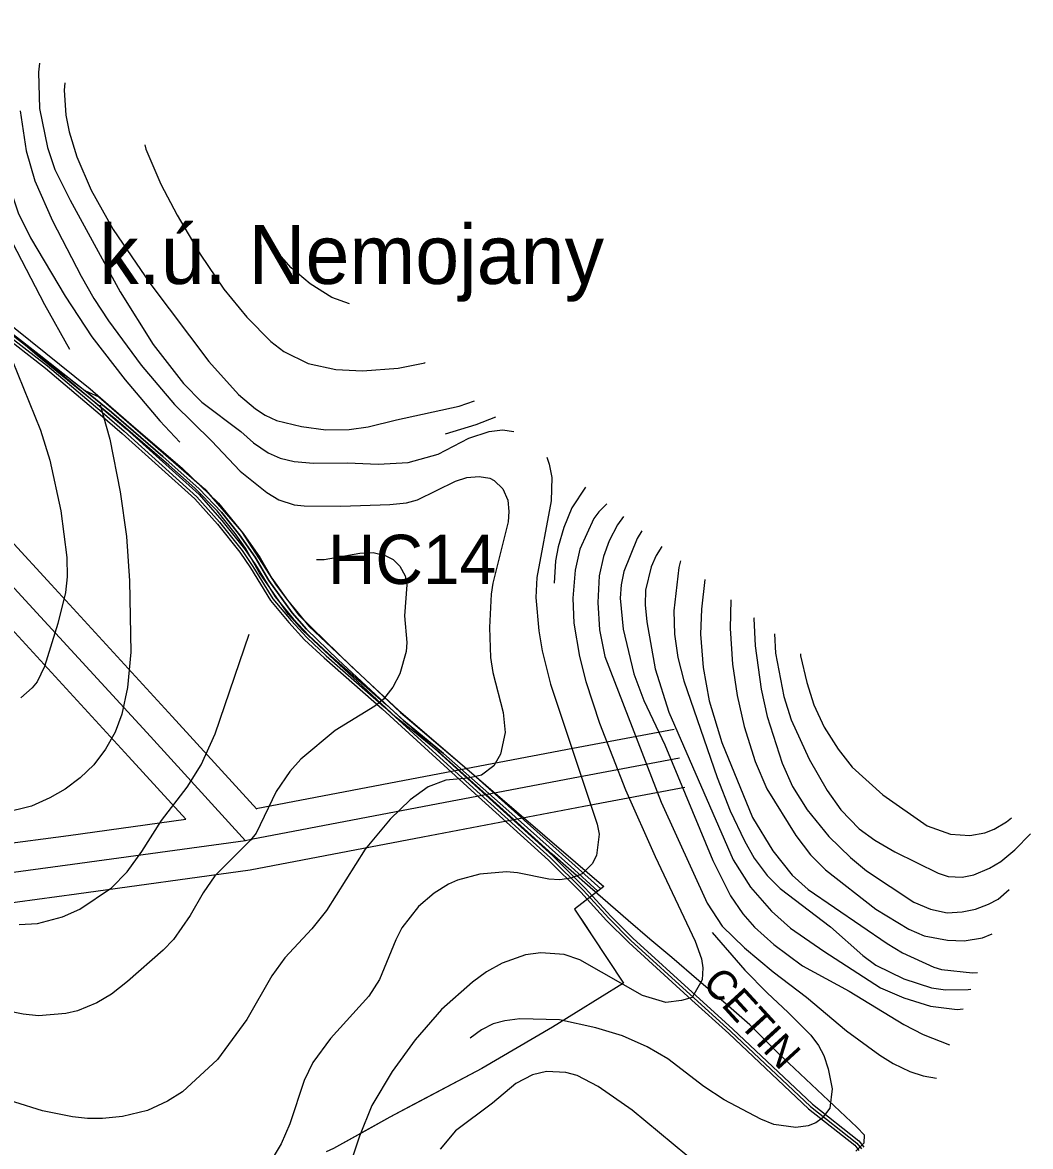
# Model space of a CAD drawing. Extents: x -1900516 to -575031, y -3809306 to -1157387.
# Drawn here: x -576727 to -576215, y -1158034 to -1157464 of the extents above; entities that cross this region are included whole.
import ezdxf

# ---------------------------------------------------------------- set-up
doc = ezdxf.new("R2010")
doc.units = 0
for name, color, linetype in [('01_OBVOD PÚ', 7, 'Continuous'), ('01_SPRÁV_HRANICE', 7, 'Continuous'), ('01_VRSTEVNICE', 7, 'Continuous'), ('02_KULTURY STAV', 7, 'Continuous'), ('03_PC_POPIS_STAV', 7, 'Continuous'), ('03_PC_STAV', 7, 'Continuous'), ('04_ZPF_OP_ORGAN', 7, 'Continuous'), ('07_ELEKTRO', 7, 'Continuous'), ('07_OCH_P A POPISY TI', 7, 'Continuous'), ('07_SDĚLOVACÍ', 7, 'Continuous')]:
    doc.layers.add(name, color=color, linetype=linetype)

msp = doc.modelspace()

# ---------------------------------------------------------------- linework, layer by layer
at = {"layer": '01_OBVOD PÚ'}
msp.add_lwpolyline([(-576728.04, -1157624.7), (-576725.06, -1157627.04), (-576722.43, -1157629.11), (-576718.49, -1157632.21), (-576717.18, -1157633.23), (-576711.95, -1157637.34), (-576706.32, -1157641.76), (-576704.25, -1157643.39), (-576701.08, -1157645.87), (-576695.26, -1157650.44), (-576688.08, -1157653.73), (-576634.44, -1157700.33), (-576615.59, -1157721.97), (-576598.08, -1157749.21), (-576586.54, -1157764.45), (-576559.98, -1157790.42), (-576535.99, -1157812.74), (-576431.68, -1157902.32), (-576433.12, -1157903.44), (-576446.46, -1157913.81), (-576440.6, -1157922.65), (-576437.53, -1157927.29), (-576429.6, -1157939.25), (-576421.57, -1157951.36), (-576457.68, -1157973.76), (-576493.58, -1157994.61), (-576530.49, -1158014.16), (-576540.36, -1158019.43), (-576550.05, -1158024.84), (-576568.92, -1158035.36)], dxfattribs=at)
at = {"layer": '01_SPRÁV_HRANICE'}
for p, q in [((-576731.39, -1157622.07), (-576718.49, -1157632.21)), ((-576718.49, -1157632.21), (-576695.26, -1157650.44)), ((-576695.26, -1157650.44), (-576688.08, -1157653.73)), ((-576633.78, -1157701.05), (-576615.59, -1157721.97)), ((-576615.59, -1157721.97), (-576598.08, -1157749.21)), ((-576598.08, -1157749.21), (-576586.54, -1157764.45)), ((-576586.54, -1157764.45), (-576559.98, -1157790.42)), ((-576559.98, -1157790.42), (-576535.99, -1157812.74)), ((-576535.99, -1157812.74), (-576431.68, -1157902.32)), ((-576433.12, -1157903.44), (-576446.46, -1157913.81)), ((-576431.68, -1157902.32), (-576433.12, -1157903.44)), ((-576446.46, -1157913.81), (-576421.57, -1157951.36))]:
    msp.add_line(p, q, dxfattribs=at)
for points in [[(-576688.08, -1157653.73), (-576661.26, -1157677.03), (-576634.44, -1157700.33), (-576633.78, -1157701.05)], [(-576421.57, -1157951.36), (-576457.68, -1157973.76), (-576493.58, -1157994.61)], [(-576493.58, -1157994.61), (-576540.36, -1158019.43), (-576568.92, -1158035.36), (-576572.73, -1158036.92)]]:
    msp.add_lwpolyline(points, dxfattribs=at)
at = {"layer": '01_VRSTEVNICE'}
for points in [[(-576744.91, -1157463.58), (-576748.9, -1157474.22), (-576751.01, -1157491.15), (-576750.02, -1157513.73), (-576747.62, -1157533.48), (-576744.94, -1157546.18), (-576739.16, -1157561.7), (-576715.74, -1157606.85), (-576703.04, -1157629.42)], [(-576738.47, -1157468.58), (-576739.02, -1157469.99), (-576740.85, -1157478.45), (-576741.84, -1157486.92), (-576741.84, -1157501.03), (-576740.01, -1157519.37), (-576735.77, -1157540.53), (-576729.14, -1157560.28), (-576722.79, -1157572.98), (-576705.16, -1157602.61), (-576691.75, -1157623.21), (-576674.82, -1157644.94), (-576657.18, -1157665.82), (-576647.03, -1157676.69)], [(-576718.26, -1157484.26), (-576718.84, -1157488.89), (-576718.28, -1157507.24), (-576714.19, -1157526.99), (-576710.38, -1157538.28), (-576702.62, -1157553.79), (-576677.36, -1157600.36), (-576660.57, -1157627.16), (-576645.19, -1157646.92), (-576635.74, -1157656.37), (-576615.99, -1157671.32), (-576609.49, -1157676.97), (-576602.16, -1157682.05), (-576595.95, -1157684.73), (-576588.9, -1157686.42), (-576579.02, -1157687.41), (-576561.81, -1157687.13), (-576546.29, -1157687.83), (-576531.05, -1157686.99), (-576515.81, -1157682.75), (-576500.15, -1157674.57), (-576489.85, -1157671.32), (-576483.08, -1157670.48), (-576477.35, -1157671.22)], [(-576705.41, -1157494.23), (-576705.72, -1157497.92), (-576704.87, -1157510.62), (-576703.18, -1157519.09), (-576699.37, -1157531.78), (-576692.04, -1157548.72), (-576680.89, -1157568.61), (-576662.26, -1157595.98), (-576632.21, -1157635.77), (-576617.11, -1157652.42), (-576608.51, -1157659.76), (-576603.57, -1157663), (-576597.93, -1157665.68), (-576585.23, -1157668.79), (-576572.81, -1157670.34), (-576560.96, -1157670.2), (-576551.36, -1157668.93), (-576536.97, -1157665.26), (-576505.09, -1157658.34), (-576497.29, -1157655.75)], [(-576728.15, -1157508.36), (-576725.05, -1157528.68), (-576720.54, -1157543.92), (-576711.65, -1157564.24), (-576697.11, -1157592.46), (-576690.62, -1157603.74), (-576683.15, -1157615.03), (-576666.64, -1157637.6), (-576649.71, -1157657.5), (-576630.94, -1157675.98), (-576616.41, -1157691.36), (-576602.86, -1157702.22), (-576596.66, -1157706.03), (-576588.9, -1157708.43), (-576583.82, -1157709), (-576565.19, -1157709.14), (-576540.36, -1157708.29), (-576531.89, -1157707.45), (-576526.25, -1157705.89), (-576507.06, -1157696.44), (-576501.14, -1157694.6), (-576494.93, -1157694.04), (-576489.57, -1157694.89), (-576487.31, -1157696.16), (-576482.94, -1157700.39), (-576480.4, -1157706.18), (-576479.83, -1157711.82), (-576480.25, -1157717.18), (-576488.01, -1157748.22), (-576488.86, -1157753.86), (-576489.71, -1157770.8), (-576489.14, -1157786.03), (-576488.01, -1157793.65), (-576482.79, -1157813.97), (-576481.67, -1157824.13), (-576484.06, -1157835.13), (-576487.59, -1157840.92), (-576493.8, -1157845.72), (-576500.57, -1157847.27), (-576511.86, -1157848.26), (-576520.89, -1157851.64), (-576529.92, -1157858.27), (-576540.22, -1157868.15), (-576552.92, -1157883.25), (-576572.53, -1157914.43), (-576579.87, -1157923.74), (-576593.69, -1157938.41), (-576600.18, -1157947.58), (-576612.88, -1157969.74), (-576627.84, -1157990.05), (-576645.61, -1158006.56), (-576653.23, -1158011.22), (-576663.39, -1158016.01), (-576676.09, -1158018.98), (-576686.25, -1158020.11), (-576693.87, -1158020.11), (-576701.49, -1158019.26), (-576716.73, -1158016.16), (-576744.94, -1158007.41)], [(-576664.84, -1157525.71), (-576664.24, -1157527.83), (-576656.62, -1157545.61), (-576648.3, -1157561.41), (-576636.58, -1157581.17), (-576624.59, -1157598.95), (-576612.88, -1157613.2), (-576600.75, -1157625.61), (-576594.12, -1157630.69), (-576581.84, -1157636.76), (-576567.73, -1157639.72), (-576554.19, -1157640.43), (-576536.13, -1157639.02), (-576522.58, -1157636.33), (-576522.38, -1157636.27)], [(-576560.84, -1157606.43), (-576569.71, -1157603.18), (-576580.85, -1157596.26), (-576590.45, -1157588.22), (-576599.05, -1157578.34), (-576601.3, -1157575.03)], [(-576732.1, -1157635.06), (-576717.71, -1157670.62), (-576713.06, -1157685.86), (-576707.41, -1157711.54), (-576704.31, -1157735.24), (-576704.17, -1157745.12), (-576705.02, -1157753.02), (-576708.96, -1157768.82), (-576715.74, -1157790.55), (-576719.41, -1157798.31), (-576721.95, -1157801.41), (-576727.73, -1157806.49)], [(-576687.38, -1157657.78), (-576682.58, -1157675.14), (-576677.22, -1157701.94), (-576674.12, -1157724.52), (-576672.56, -1157747.09), (-576671.86, -1157783.21), (-576673.55, -1157801.27), (-576676.51, -1157814.82), (-576679.9, -1157823.85), (-576684.7, -1157832.59), (-576690.62, -1157840.5), (-576697.54, -1157847.13), (-576705.16, -1157852.77), (-576713.06, -1157857.28), (-576722.37, -1157861.52), (-576736.76, -1157865.04)], [(-576486.68, -1157663.98), (-576496.62, -1157667.94), (-576512.28, -1157672.59)], [(-576460.57, -1157684.25), (-576459.37, -1157687.83), (-576458.1, -1157694.61), (-576458.39, -1157706.46), (-576465.72, -1157745.4), (-576466.15, -1157755.56), (-576464.59, -1157772.49), (-576462.9, -1157782.65), (-576458.81, -1157799.58), (-576434.96, -1157870.69), (-576433.98, -1157875.77), (-576435.39, -1157886.49), (-576437.5, -1157890.72), (-576442.72, -1157895.8), (-576448.37, -1157898.06), (-576454.01, -1157898.91), (-576459.66, -1157898.62), (-576475.46, -1157895.38), (-576481.1, -1157894.82), (-576494.65, -1157895.94), (-576505.93, -1157899.05), (-576510.45, -1157901.02), (-576517.79, -1157905.68), (-576525.69, -1157912.45), (-576534.15, -1157923.32), (-576537.26, -1157929.38), (-576545.58, -1157949.42), (-576550.94, -1157958.03), (-576570.41, -1157979.47), (-576579.44, -1157991.6), (-576583.82, -1158000.78), (-576591.15, -1158022.79), (-576595.53, -1158032.95), (-576602.58, -1158044.8)], [(-576440.88, -1157699.53), (-576447.89, -1157710.02), (-576451.89, -1157720), (-576454.86, -1157729.88), (-576456.13, -1157736.93), (-576456.83, -1157748.22)], [(-576440.88, -1157699.53), (-576447.89, -1157710.02), (-576451.89, -1157720), (-576454.86, -1157729.88), (-576456.13, -1157736.93), (-576456.83, -1157748.22)], [(-576430.05, -1157707.93), (-576434.12, -1157711.96), (-576436.66, -1157715.35), (-576443.85, -1157731.01), (-576446.25, -1157741.73), (-576447.38, -1157755.84), (-576446.82, -1157768.54), (-576443.99, -1157785.47), (-576440.75, -1157798.17), (-576433.83, -1157819.33), (-576420.71, -1157853.19), (-576405.62, -1157887.06), (-576385.3, -1157929.95), (-576382.05, -1157938.98), (-576381.35, -1157943.49), (-576381.63, -1157949.7), (-576386.85, -1157958.59), (-576392.21, -1157960.14), (-576400.11, -1157961.13), (-576411.97, -1157957.6), (-576443.85, -1157939.54), (-576451.75, -1157936.86), (-576463.61, -1157935.87), (-576471.51, -1157937), (-576483.36, -1157941.24), (-576491.26, -1157945.61), (-576498.31, -1157950.83), (-576514.12, -1157964.66), (-576527.38, -1157980.18), (-576539.09, -1157996.26), (-576549.39, -1158013.48), (-576555.74, -1158029), (-576561.52, -1158046.35)], [(-576421.69, -1157714.42), (-576424.66, -1157718.59), (-576428.9, -1157726.78), (-576431.86, -1157734.68), (-576433.98, -1157744.55), (-576434.68, -1157758.1), (-576433.83, -1157771.92), (-576431.15, -1157785.47), (-576402.51, -1157859.4), (-576379.09, -1157910.76), (-576371.47, -1157922.47), (-576360.18, -1157933.48), (-576345.65, -1157945.61), (-576328.72, -1157958.45), (-576308.4, -1157975.52), (-576291.47, -1157987.94), (-576284.7, -1157992.17), (-576276.23, -1157996.12), (-576269.46, -1157998.38), (-576262.63, -1157999.63)], [(-576412.33, -1157721.68), (-576414.79, -1157725.51), (-576421.42, -1157742.29), (-576422.83, -1157749.07), (-576423.39, -1157755.84), (-576421.84, -1157771.64), (-576416.34, -1157794.22), (-576411.4, -1157807.76), (-576400.68, -1157830.34), (-576376.27, -1157889.03), (-576367.24, -1157907.09), (-576361.03, -1157916.12), (-576355.1, -1157922.89), (-576345.23, -1157931.64), (-576330.7, -1157942.51), (-576306.99, -1157955.49), (-576279.34, -1157972.42), (-576269.46, -1157977.35), (-576256.11, -1157982.67)], [(-576402.17, -1157729.57), (-576405.05, -1157734.25), (-576407.59, -1157740.04), (-576410.41, -1157751.89), (-576410.7, -1157759.23), (-576409.85, -1157767.97), (-576405.62, -1157791.68), (-576398.56, -1157813.69), (-576365.97, -1157888.75), (-576357.08, -1157902.58), (-576346.5, -1157914.85), (-576336.9, -1157923.46), (-576319.97, -1157935.17), (-576291.19, -1157953.65), (-576279.34, -1157958.87), (-576265.79, -1157963.1), (-576252.25, -1157964.8), (-576249.1, -1157964.44)], [(-576577.56, -1157736.23), (-576573.66, -1157736.23), (-576555.6, -1157732.98), (-576548.83, -1157732.7), (-576542.62, -1157734.25), (-576538.67, -1157736.23), (-576535.28, -1157739.61), (-576532.46, -1157744.55), (-576531.61, -1157749.07), (-576532.88, -1157764.87), (-576531.75, -1157778.42), (-576532.04, -1157782.93), (-576535.28, -1157794.22), (-576538.81, -1157800.99), (-576543.46, -1157807.2), (-576547.98, -1157810.72), (-576568.01, -1157823), (-576585.51, -1157837.67), (-576591.15, -1157843.88), (-576598.07, -1157854.04), (-576608.22, -1157875.2), (-576611.05, -1157878.73), (-576629.25, -1157896.79), (-576635.17, -1157905.54), (-576641.66, -1157916.97), (-576650.27, -1157929.1), (-576655.49, -1157934.6), (-576673.55, -1157950.55), (-576681.73, -1157956.9), (-576689.07, -1157961.27), (-576698.95, -1157965.36), (-576704.87, -1157966.77), (-576718.7, -1157967.9), (-576726.6, -1157967.05), (-576736.48, -1157965.08)], [(-576392.64, -1157736.97), (-576393.62, -1157740.32), (-576396.16, -1157762.33), (-576395.74, -1157774.18), (-576394.05, -1157786.03), (-576390.94, -1157797.89), (-576374.15, -1157846.99), (-576367.52, -1157863.92), (-576360.18, -1157879.16), (-576355.25, -1157887.9), (-576348.76, -1157896.65), (-576342.12, -1157903.28), (-576316.59, -1157922.75), (-576300.08, -1157937.28), (-576293.45, -1157942.22), (-576279.34, -1157949.14), (-576265.23, -1157953.65), (-576258.18, -1157954.78), (-576246.6, -1157954.64), (-576245.24, -1157954.39)], [(-576380.42, -1157746.44), (-576382.05, -1157761.48), (-576382.48, -1157774.18), (-576381.21, -1157791.11), (-576378.1, -1157808.04), (-576371.75, -1157829.21), (-576356.09, -1157867.3), (-576345.79, -1157884.23), (-576336.06, -1157896.51), (-576327.87, -1157903.71), (-576287.8, -1157931.22), (-576279.9, -1157936.02), (-576264.1, -1157943.21), (-576260.15, -1157944.34), (-576244.35, -1157946.03), (-576241.95, -1157945.86)], [(-576367.12, -1157756.77), (-576367.52, -1157771.36), (-576366.25, -1157789.42), (-576363.85, -1157805.22), (-576360.33, -1157821.03), (-576354.82, -1157838.8), (-576348.9, -1157852.63), (-576334.08, -1157876.33), (-576326.74, -1157886.21), (-576319.13, -1157893.83), (-576293.45, -1157913.72), (-576276.8, -1157923.88), (-576268.9, -1157927.27), (-576257.05, -1157929.53), (-576248.58, -1157929.81), (-576239.27, -1157928.26), (-576234.4, -1157926.23)], [(-576355.37, -1157765.88), (-576355.39, -1157766.28), (-576354.82, -1157780.11), (-576351.72, -1157802.12), (-576348.61, -1157815.95), (-576341.14, -1157839.65), (-576335.78, -1157851.5), (-576328.44, -1157863.35), (-576317.43, -1157876.9), (-576306.43, -1157887.62), (-576298.24, -1157894.39), (-576274.26, -1157910.2), (-576265.79, -1157913.86), (-576257.33, -1157915.56), (-576249.71, -1157915.13), (-576242.94, -1157913.86), (-576236.31, -1157911.32), (-576231.37, -1157908.64), (-576225.79, -1157903.84)], [(-576728.58, -1157921.62), (-576719.27, -1157921.06), (-576706.57, -1157917.67), (-576697.82, -1157913.72), (-576681.73, -1157903), (-576673.69, -1157894.82), (-576666.35, -1157884.52), (-576656.34, -1157868.71), (-576643.22, -1157851.78), (-576636.16, -1157840.5), (-576629.11, -1157824.69), (-576611.77, -1157774.08)], [(-576345.01, -1157773.93), (-576344.38, -1157783.78), (-576340.29, -1157805.79), (-576336.48, -1157817.64), (-576327.31, -1157837.67), (-576318.28, -1157853.48), (-576311.22, -1157863.35), (-576302.05, -1157872.95), (-576294.01, -1157878.73), (-576283.85, -1157884.66), (-576261.84, -1157895.52), (-576256.76, -1157897.21), (-576249.71, -1157897.5), (-576243.78, -1157896.37), (-576235.74, -1157892.98), (-576229.96, -1157889.59), (-576222.9, -1157883.67), (-576214.94, -1157875.61)], [(-576331.78, -1157784.19), (-576331.68, -1157785.19), (-576328.58, -1157798.73), (-576325.05, -1157810.02), (-576319.69, -1157821.31), (-576312.64, -1157832.59), (-576305.44, -1157841.62), (-576289.92, -1157855.73), (-576267.49, -1157871.53), (-576255.64, -1157875.77), (-576245.76, -1157876.33), (-576238.14, -1157875.06), (-576233.34, -1157873.09), (-576227.13, -1157869.42), (-576224.57, -1157867.4)], [(-576376.55, -1157925.57), (-576360.04, -1157944.76), (-576348.76, -1157956.33), (-576338.03, -1157966.21), (-576326.46, -1157977.78), (-576322.65, -1157983), (-576319.97, -1157988.08), (-576317.71, -1157994.85), (-576315.74, -1158005.01), (-576316.87, -1158014.74), (-576320.68, -1158019.97), (-576323.92, -1158022.22), (-576327.88, -1158023.77), (-576334.08, -1158024.6), (-576345.23, -1158023.07), (-576351.86, -1158020.39), (-576370.48, -1158010.51), (-576380.78, -1158003.74), (-576399.13, -1157989.77), (-576409.71, -1157983.7), (-576422.12, -1157978.06), (-576435.67, -1157974.11), (-576454.15, -1157970.02), (-576474.33, -1157969.45), (-576481.95, -1157970.44), (-576487.87, -1157971.99), (-576493.8, -1157974.96), (-576499.58, -1157979.33)], [(-576382.62, -1158044.66), (-576417.33, -1158015.87), (-576434.54, -1158003.88), (-576445.26, -1157998.24), (-576450.91, -1157996.68), (-576460.78, -1157996.26), (-576467.84, -1157997.81), (-576476.3, -1158002.33), (-576488.16, -1158012.21), (-576506.92, -1158026.31), (-576514.82, -1158035.63)]]:
    msp.add_lwpolyline(points, dxfattribs=at)
at = {"layer": '02_KULTURY STAV'}
msp.add_lwpolyline([(-576728.04, -1157624.7), (-576725.06, -1157627.04), (-576722.43, -1157629.11), (-576718.49, -1157632.21), (-576717.18, -1157633.23), (-576711.95, -1157637.34), (-576706.32, -1157641.76), (-576704.25, -1157643.39), (-576701.08, -1157645.87), (-576695.28, -1157650.41), (-576695.21, -1157650.47), (-576681.63, -1157661.5), (-576655.57, -1157684), (-576637.15, -1157700.31), (-576625.84, -1157712.17), (-576616.74, -1157723.66), (-576608.74, -1157735.11), (-576601.7, -1157746.91), (-576589.96, -1157763.27), (-576582.6, -1157771.64), (-576566.5, -1157787.11), (-576533.42, -1157818.03), (-576513.15, -1157834.81), (-576481.45, -1157862.74), (-576448.48, -1157892.13), (-576434.68, -1157904.65), (-576446.46, -1157913.81), (-576440.6, -1157922.65), (-576437.53, -1157927.29), (-576429.6, -1157939.25), (-576421.57, -1157951.36), (-576457.68, -1157973.76), (-576493.58, -1157994.61), (-576530.49, -1158014.16), (-576540.36, -1158019.43), (-576550.05, -1158024.84), (-576568.92, -1158035.36)], dxfattribs=at)
msp.add_lwpolyline([(-576695.21, -1157650.47), (-576688.08, -1157653.73), (-576634.44, -1157700.33), (-576615.59, -1157721.97), (-576598.08, -1157749.21), (-576586.54, -1157764.45), (-576559.98, -1157790.42), (-576535.99, -1157812.74), (-576431.68, -1157902.32), (-576433.12, -1157903.44), (-576434.68, -1157904.65), (-576448.48, -1157892.13), (-576481.45, -1157862.74), (-576513.15, -1157834.81), (-576533.42, -1157818.03), (-576566.5, -1157787.11), (-576582.6, -1157771.64), (-576589.96, -1157763.27), (-576601.7, -1157746.91), (-576608.74, -1157735.11), (-576616.74, -1157723.66), (-576625.84, -1157712.17), (-576637.15, -1157700.31), (-576655.57, -1157684), (-576681.63, -1157661.5)], close=True, dxfattribs=at)
at = {"layer": '03_PC_STAV'}
msp.add_lwpolyline([(-576782.18, -1157576.41), (-576761.16, -1157594.51), (-576692.46, -1157649.63), (-576670.36, -1157668.91), (-576645.86, -1157689.9), (-576627.28, -1157707.7), (-576614.87, -1157722.99), (-576606.14, -1157735.47), (-576600.23, -1157745.64), (-576592.31, -1157756.83), (-576581.51, -1157770.07), (-576552.51, -1157797.3), (-576534.96, -1157813.88), (-576501.47, -1157842.44), (-576433.12, -1157903.44)], dxfattribs=at)
at = {"layer": '04_ZPF_OP_ORGAN'}
for points in [[(-576303.7, -1158036.7), (-576299.5, -1158032.5), (-576299.2, -1158028.5), (-576303.1, -1158024.5), (-576323.25, -1158005.55), (-576343.4, -1157986.6), (-576357.5, -1157972.5), (-576369.7, -1157961.9), (-576383.4, -1157950.1), (-576397.1, -1157938.3), (-576408.2, -1157928.95), (-576419.3, -1157919.6), (-576438.6, -1157902.75), (-576457.9, -1157885.9), (-576486.35, -1157860.2), (-576514.8, -1157834.5), (-576526, -1157825.4), (-576537.2, -1157816.3), (-576570.9, -1157784.9), (-576584.6, -1157772.1), (-576591.8, -1157764.1), (-576599.2, -1157753.52), (-576606.6, -1157742.94), (-576613.66, -1157730.55), (-576618.8, -1157723), (-576623.45, -1157717.3), (-576628.1, -1157711.6), (-576639.3, -1157700.1), (-576652.6, -1157688.4), (-576666, -1157676.8), (-576679.4, -1157665.2), (-576699.4, -1157648.95), (-576719.4, -1157632.7), (-576726.6, -1157626.5), (-576737.84, -1157617.37)], [(-576570.9, -1157784.9), (-576584.6, -1157772.1), (-576591.8, -1157764.1), (-576599.2, -1157753.52), (-576606.6, -1157742.94), (-576613.66, -1157730.55), (-576618.8, -1157723), (-576623.45, -1157717.3), (-576628.1, -1157711.6), (-576639.3, -1157700.1), (-576652.6, -1157688.4), (-576666, -1157676.8), (-576679.4, -1157665.2), (-576699.4, -1157648.95), (-576719.4, -1157632.7), (-576726.6, -1157626.5), (-576737.84, -1157617.37)], [(-576303.7, -1158036.7), (-576299.5, -1158032.5), (-576299.2, -1158028.5), (-576303.1, -1158024.5), (-576323.25, -1158005.55), (-576343.4, -1157986.6), (-576357.5, -1157972.5), (-576369.7, -1157961.9), (-576383.4, -1157950.1), (-576397.1, -1157938.3), (-576408.2, -1157928.95), (-576419.3, -1157919.6), (-576438.6, -1157902.75), (-576457.9, -1157885.9), (-576486.35, -1157860.2), (-576514.8, -1157834.5), (-576526, -1157825.4), (-576537.2, -1157816.3), (-576570.9, -1157784.9)]]:
    msp.add_lwpolyline(points, dxfattribs=at)
at = {"layer": '07_ELEKTRO'}
for points in [[(-576829.65, -1157643.61), (-576786.08, -1157691.03), (-576723.45, -1157759.12), (-576661.94, -1157826.12), (-576613.64, -1157879.01)], [(-576393.24, -1157837.13), (-576444.58, -1157846.72), (-576526.46, -1157862.4)], [(-576526.46, -1157862.4), (-576610.73, -1157878.46), (-576613.64, -1157879.01)], [(-576613.64, -1157879.01), (-576701.48, -1157891.16), (-576783, -1157902.14), (-576868.21, -1157913.92), (-576958.94, -1157926.41), (-577060.41, -1157940.16), (-577166.82, -1157954.4), (-577258.94, -1157956.97), (-577319.09, -1157965.17), (-577363.1, -1157971.3), (-577443.48, -1157983.02), (-577522.09, -1157993.86), (-577610.84, -1158006.39), (-577703.33, -1158019.18), (-577796.56, -1158031.66)]]:
    msp.add_lwpolyline(points, dxfattribs=at)
at = {"layer": '07_OCH_P A POPISY TI'}
for p, q in [((-576447.37, -1157831.98), (-576395.99, -1157822.38)), ((-576529.27, -1157847.67), (-576447.37, -1157831.98)), ((-576608.21, -1157862.71), (-576529.27, -1157847.67)), ((-576441.79, -1157861.46), (-576390.48, -1157851.87)), ((-576523.64, -1157877.13), (-576441.79, -1157861.46)), ((-576703.51, -1157876.3), (-576643.95, -1157868.06)), ((-576785.03, -1157887.28), (-576703.51, -1157876.3)), ((-576611.21, -1157893.82), (-576523.64, -1157877.13)), ((-576699.45, -1157906.02), (-576611.21, -1157893.82)), ((-576780.97, -1157917), (-576699.45, -1157906.02))]:
    msp.add_line(p, q, dxfattribs=at)
for points in [[(-576737.44, -1157618.14), (-576713.28, -1157636.7), (-576685.53, -1157660.32), (-576674.27, -1157669.93), (-576637.24, -1157703.29), (-576625.62, -1157716.38), (-576614.14, -1157730.75), (-576608.6, -1157738.91), (-576598.57, -1157755.26), (-576589.34, -1157766.3), (-576581.5, -1157774.85), (-576571.63, -1157784), (-576542.24, -1157809.87), (-576495.2, -1157852.75), (-576457.62, -1157886.7), (-576441.09, -1157903.04), (-576428.08, -1157917.39), (-576416.93, -1157928.56), (-576384.85, -1157957.69), (-576366.08, -1157974.76), (-576325.69, -1158012.86), (-576302.1, -1158031.48), (-576299.6, -1158034.63)], [(-576739.28, -1157620.52), (-576715.16, -1157639.04), (-576687.47, -1157662.6), (-576676.25, -1157672.19), (-576639.38, -1157705.41), (-576627.92, -1157718.32), (-576616.56, -1157732.53), (-576611.12, -1157740.53), (-576601.01, -1157757.02), (-576591.6, -1157768.28), (-576583.62, -1157776.97), (-576573.65, -1157786.22), (-576544.24, -1157812.11), (-576497.22, -1157854.97), (-576459.68, -1157888.88), (-576443.25, -1157905.12), (-576430.26, -1157919.45), (-576419.01, -1157930.74), (-576386.87, -1157959.91), (-576368.12, -1157976.96), (-576327.65, -1158015.14), (-576304.24, -1158033.62), (-576302.1, -1158036.31)], [(-576818.6, -1157633.46), (-576775.04, -1157680.88), (-576712.4, -1157748.97), (-576650.88, -1157815.99), (-576607.88, -1157863.07)], [(-576840.69, -1157653.76), (-576797.12, -1157701.18), (-576734.49, -1157769.27), (-576673, -1157836.25), (-576643.95, -1157868.06)]]:
    msp.add_lwpolyline(points, dxfattribs=at)
at = {"layer": '07_SDĚLOVACÍ'}
msp.add_lwpolyline([(-576738.36, -1157619.33), (-576714.22, -1157637.87), (-576686.5, -1157661.46), (-576675.26, -1157671.06), (-576638.31, -1157704.35), (-576626.77, -1157717.35), (-576615.35, -1157731.64), (-576609.86, -1157739.72), (-576599.79, -1157756.14), (-576590.47, -1157767.29), (-576582.56, -1157775.91), (-576572.64, -1157785.11), (-576543.24, -1157810.99), (-576496.21, -1157853.86), (-576458.65, -1157887.79), (-576442.17, -1157904.08), (-576429.17, -1157918.42), (-576417.97, -1157929.65), (-576385.86, -1157958.8), (-576367.1, -1157975.86), (-576326.67, -1158014), (-576303.17, -1158032.55), (-576300.85, -1158035.47)], dxfattribs=at)

# ---------------------------------------------------------------- texts
at = {"layer": '01_SPRÁV_HRANICE'}
msp.add_text('k.ú. Nemojany', height=30, dxfattribs=at).set_placement((-576687.93, -1157596.34))
at = {"layer": '03_PC_POPIS_STAV'}
msp.add_text('HC14', height=25, dxfattribs=at).set_placement((-576571.8, -1157748.67))
at = {"layer": '07_OCH_P A POPISY TI'}
msp.add_text('CETIN', height=15, rotation=312.465, dxfattribs=at).set_placement((-576382.22, -1157951.85))

doc.saveas('drawing.dxf')
